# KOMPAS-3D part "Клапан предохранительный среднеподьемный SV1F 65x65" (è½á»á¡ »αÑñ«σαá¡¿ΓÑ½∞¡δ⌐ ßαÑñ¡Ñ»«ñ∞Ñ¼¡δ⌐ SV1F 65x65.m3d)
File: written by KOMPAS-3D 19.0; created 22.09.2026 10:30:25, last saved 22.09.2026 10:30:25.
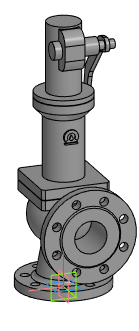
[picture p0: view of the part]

Document properties: Автор: Евгений; Полное имя файла: Z:\3.Личные\sachek\Dendor\_3D для проектировщиков\5.8 SV1F. Клапан предохранительный среднеподьемный\SV1F_STP\Клапан предохранительный среднеподьемный SV1F 65x65.m3d

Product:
- Part/product: Клапан предохранительный среднеподьемный SV1F 65x65
    Масса: 35.9633

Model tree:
1. Операция без истории:1  (labels: Клапан предохранительный среднеподьемный SV1F 65x65)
